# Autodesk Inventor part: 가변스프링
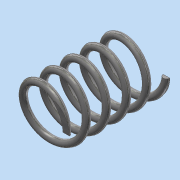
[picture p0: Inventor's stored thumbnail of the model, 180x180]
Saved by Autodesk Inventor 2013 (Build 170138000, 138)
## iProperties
Created: 2018-10
Part Number: 가변스프링
Material: 스테인리스강
Document SubType Name: Modeling
Designer: Administrator
Density: 8.08 g/cm^3
Mass: 6.30653 g
Surface Area: 15.7977 cm^2
Volume: 0.780512 cm^3
Author: Administrator
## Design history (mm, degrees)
sketch "스케치1"
  geometry: L1 (0, 0)-(0, 25.77); L2 (0, 0)-(8, 0); L3 (0, 25.77)-(8, 25.77); C1 r 1 at (8, 0)
  constraints: 6 end point, 1 centre point, 1 coincident, 1 parallel, 1 perpendicular, 1 vertical
  dimensions: "d0" = 25.76996 distance of L1.start L1.end (derived); "d1" = 8 distance of L1.start L2.end; "d2" = 2 diameter of C1; "d3" = 8 distance of L1.end L3.end
feature "코일1" sketch "스케치1" pitch "d4" = 25.76996 (= d0); turns "d6" = 5; dims "d5" = 25.76996 (= d0), "d7" = 0, angle "d8" = 90 deg, angle "d9" = 90 deg, "d10" = 0, "d11" = 0
sketch "스케치2"
  geometry: L1 (25.77, 11)-(0, 11); L2 (0, 11)-(0, -11); L3 (0, -11)-(25.77, -11); L4 (25.77, -11)-(25.77, 11); 2 further points
  constraints: 8 end point, 2 parallel, 1 coincident, 1 horizontal, 1 midpoint, 1 perpendicular
  dimensions: "d12" = 25.76996 distance of L2.end L3.end (derived); "d16" = 22 distance of L3.end L1.start
extrude "돌출1" sketch "스케치2" stored distance "d14" = 0; taper "d15" = 0 deg
node "솔리드1"
